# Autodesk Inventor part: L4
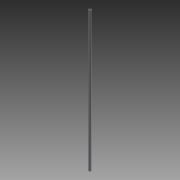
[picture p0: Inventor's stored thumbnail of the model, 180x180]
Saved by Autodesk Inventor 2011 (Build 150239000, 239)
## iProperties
Created: 2014-02
Part Number: L4
Document SubType Name: Modeling
Designer: Evgeny
Density: 1 g/cm^3
Author: Evgeny
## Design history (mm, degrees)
sketch "Эскиз1"
  geometry: C1 r 4 at (0, 0); 1 further point
  constraints: 1 centre point, 1 coincident
  dimensions: "d0" = 8 diameter of C1
extrude "Выдавливание1" new body sketch "Эскиз1" distance "d1" = 458; taper "d2" = 0 deg
feature "Оболочка1" dims "d3" = 1
node "Твердое тело1"
